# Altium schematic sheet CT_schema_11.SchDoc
size 147 x 119 mm
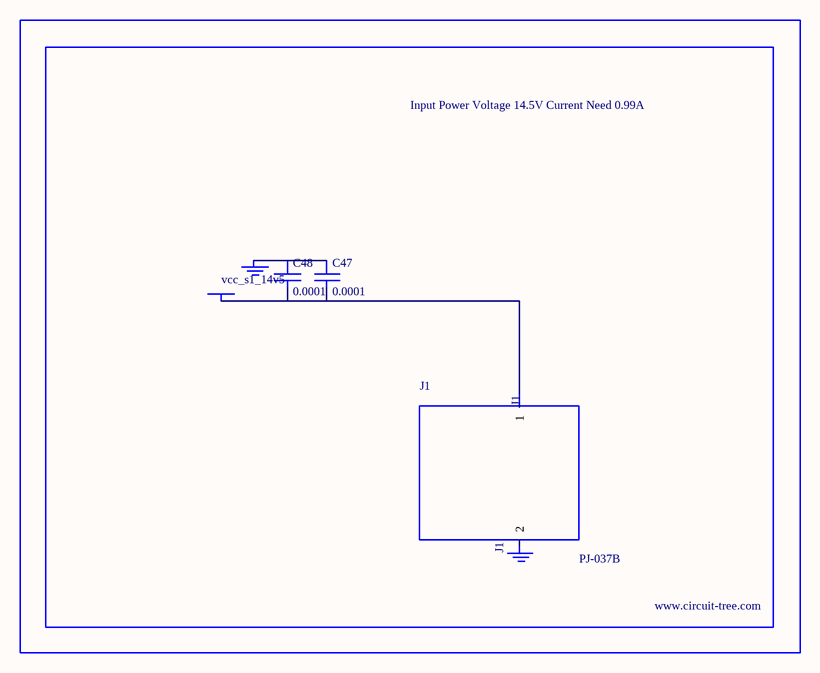
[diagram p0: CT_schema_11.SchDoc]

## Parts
BORDER10  (no value)
C47  0.0001  [EXV-9H]
C48  0.0001  [EXV-9H]
GND_INSTANCE_10_0  (no value)
GND_INSTANCE_10_1  (no value)
J1  PJ-037B  [PJ-037B_PACKAGE]
POWER_INSTANCE_10_0  vcc_s1_14v5

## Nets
NetC47_1: C47.1 C48.1 GND_INSTANCE_10_0.0(GND)
NetC47_2: C47.2 C48.2 J1.1 POWER_INSTANCE_10_0.0(PWR)

Not connected (* = marked no-connect by the designer): GND_INSTANCE_10_1 0(GND); J1 2

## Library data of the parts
BORDER10 = BORDER_PAGE10
C47 C48 = EDK107M035A9HAA
GND_INSTANCE_10_0 GND_INSTANCE_10_1 = GND
POWER_INSTANCE_10_0 = PWR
